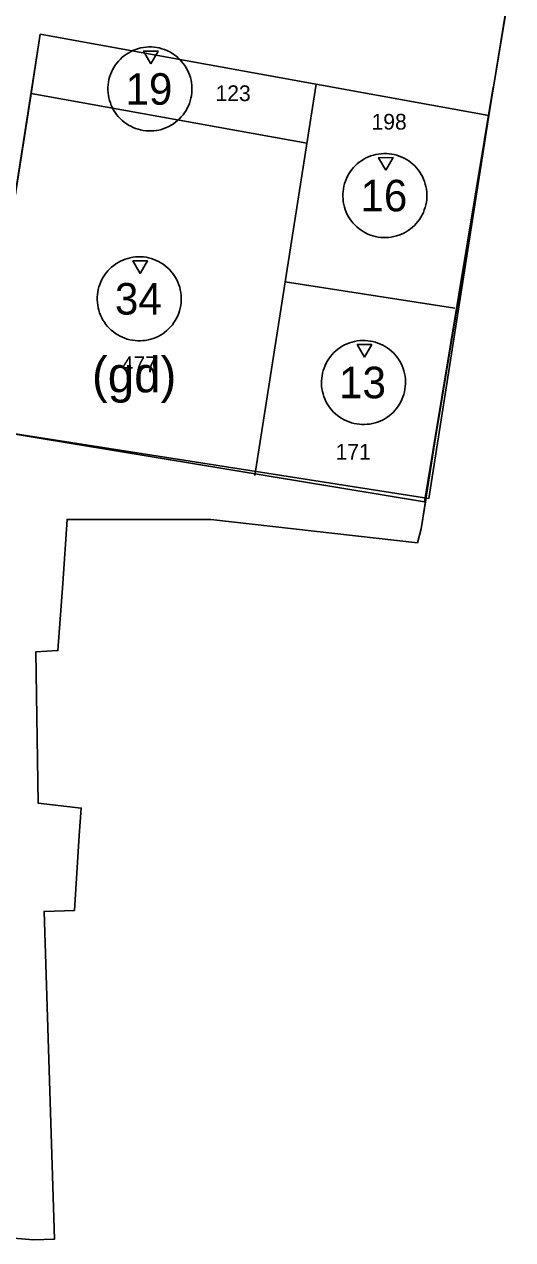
# Model space of a CAD drawing. Extents: x 104705 to 105186, y 424858 to 425816.
# Drawn here: x 105048.3 to 105083.1, y 424958.5 to 425045.2 of the extents above; entities that cross this region are included whole.
import ezdxf

# ---------------------------------------------------------------- set-up
doc = ezdxf.new("R2010")
doc.units = 0
for name, color, linetype in [('BP_ALG_bestemminggrens', 7, 'Continuous'), ('BP_BPG_Plangebied', 7, 'Continuous'), ('BP_BV_Bouwvlak', 7, 'Continuous'), ('BP_DB_Waarde - Archeologie - 3', 7, 'Continuous'), ('BP_EB_Verkeer', 7, 'Continuous'), ('BP_EB_Wonen', 7, 'Continuous'), ('BP_FA_gemengd', 7, 'Continuous'), ('BP_MV_maatvoering', 7, 'Continuous'), ('BP_TXT_tekst', 7, 'Continuous'), ('Default', 7, 'Continuous')]:
    doc.layers.add(name, color=color, linetype=linetype)

msp = doc.modelspace()

# ---------------------------------------------------------------- linework, layer by layer
at = {"layer": 'BP_ALG_bestemminggrens'}
for p, q in [((105046.867, 425028.264), (105049.408, 425044.533)), ((105081.418, 425038.738), (105049.408, 425044.533)), ((105081.418, 425038.738), (105076.846, 425011.136)), ((105045.014, 425016.408), (105076.846, 425011.136)), ((105045.014, 425016.407), (105076.846, 425011.136)), ((105076.846, 425011.136), (105076.846, 425011.136))]:
    msp.add_line(p, q, dxfattribs=at)
msp.add_lwpolyline([(105050.429, 424958.51), (105049.681, 424981.898), (105051.841, 424981.967)], dxfattribs=at)
at = {"layer": 'BP_BPG_Plangebied'}
msp.add_line((105051.841, 424981.967), (105051.841, 424981.967), dxfattribs=at)
for points in [[(105076.336, 425008.227), (105076.608, 425009.22), (105077.579, 425015.433), (105083.131, 425049.138)], [(105051.841, 424981.967), (105052.177, 424987.331), (105052.335, 424989.277), (105049.259, 424989.62), (105049.088, 425000.426), (105050.662, 425000.525), (105051.005, 425005.321), (105051.324, 425009.889), (105061.571, 425009.88), (105076.336, 425008.227)], [(105051.841, 424981.967), (105049.681, 424981.898), (105050.429, 424958.51)], [(104992.458, 424966.409), (105038.397, 424959.322), (105048.93, 424958.462), (105050.429, 424958.51)]]:
    msp.add_lwpolyline(points, dxfattribs=at)
at = {"layer": 'BP_BV_Bouwvlak'}
for p, q in [((105046.867, 425028.264), (105049.409, 425044.533)), ((105049.408, 425044.533), (105081.418, 425038.738)), ((105081.749, 425040.746), (105076.846, 425011.136)), ((105076.846, 425011.136), (105045.014, 425016.407))]:
    msp.add_line(p, q, dxfattribs=at)
at = {"layer": 'BP_DB_Waarde - Archeologie - 3'}
msp.add_line((105049.681, 424981.898), (105051.841, 424981.967), dxfattribs=at)
for points in [[(105076.336, 425008.227), (105076.608, 425009.22), (105077.579, 425015.433), (105083.131, 425049.138)], [(105051.841, 424981.967), (105052.177, 424987.331), (105052.335, 424989.277), (105049.259, 424989.62), (105049.088, 425000.426), (105050.662, 425000.525), (105051.005, 425005.321), (105051.324, 425009.889), (105061.571, 425009.88), (105076.336, 425008.227)], [(104992.458, 424966.409), (105038.397, 424959.322), (105048.93, 424958.462), (105050.429, 424958.51), (105049.681, 424981.898), (105049.681, 424981.898)]]:
    msp.add_lwpolyline(points, dxfattribs=at)
at = {"layer": 'BP_EB_Verkeer'}
for p, q in [((105081.418, 425038.738), (105083.131, 425049.138)), ((105048.674, 425039.829), (105049.408, 425044.533)), ((105049.408, 425044.533), (105081.418, 425038.738)), ((105046.866, 425028.264), (105048.674, 425039.829)), ((105064.746, 425013.14), (105045.014, 425016.408)), ((105076.846, 425011.136), (105064.746, 425013.14)), ((105076.608, 425009.22), (105076.951, 425011.417)), ((105076.894, 425011.426), (105076.846, 425011.136)), ((105076.951, 425011.417), (105076.894, 425011.426)), ((105061.571, 425009.88), (105076.336, 425008.227)), ((105076.336, 425008.227), (105076.608, 425009.22)), ((105050.662, 425000.525), (105051.005, 425005.321)), ((105049.088, 425000.426), (105050.662, 425000.525)), ((105049.259, 424989.62), (105049.088, 425000.426)), ((105051.841, 424981.967), (105052.177, 424987.331)), ((105049.681, 424981.898), (105051.841, 424981.967)), ((105050.429, 424958.51), (105049.681, 424981.898))]:
    msp.add_line(p, q, dxfattribs=at)
for points in [[(105051.005, 425005.321), (105051.324, 425009.889), (105061.571, 425009.88)], [(105052.177, 424987.331), (105052.335, 424989.277), (105049.259, 424989.62)], [(105041.81, 424959.043), (105048.93, 424958.462), (105050.429, 424958.51)]]:
    msp.add_lwpolyline(points, dxfattribs=at)
at = {"layer": 'BP_EB_Wonen'}
for points in [[(105077.145, 425011.387), (105081.418, 425038.738), (105049.408, 425044.533), (105049.287, 425043.758), (105046.856, 425028.204), (105015.703, 425033.072), (105014.92, 425028), (105009.674, 425028.81), (105008.627, 425022.021), (105005.662, 425022.479), (105002.768, 425003.717), (104999.803, 425004.175), (104994.246, 424968.157), (105006.105, 424966.327), (105005.8, 424964.351), (105038.397, 424959.322)], [(105038.397, 424959.322), (105041.81, 424959.043), (105043.061, 424970.744), (105038.007, 424971.524), (105008.124, 424976.134), (105012.156, 425002.269), (105015.121, 425001.811), (105018.016, 425020.573), (105045.014, 425016.407), (105077.145, 425011.387)]]:
    msp.add_lwpolyline(points, dxfattribs=at)
at = {"layer": 'BP_FA_gemengd'}
msp.add_lwpolyline([(105045.014, 425016.408), (105077.145, 425011.387), (105081.418, 425038.738), (105049.408, 425044.533), (105049.287, 425043.758), (105046.856, 425028.204), (105015.703, 425033.072), (105014.92, 425028), (105009.674, 425028.81), (105008.627, 425022.021), (105045.066, 425016.4)], dxfattribs=at)
at = {"layer": 'BP_MV_maatvoering'}
for p, q in [((105048.747, 425040.306), (105068.434, 425036.742)), ((105069.094, 425040.969), (105064.729, 425013.03)), ((105066.89, 425026.862), (105079.007, 425024.969))]:
    msp.add_line(p, q, dxfattribs=at)
for points in [[(105059.901, 425039.245), (105059.81, 425039.08), (105059.708, 425038.921), (105059.597, 425038.77), (105059.475, 425038.626), (105059.346, 425038.489), (105059.208, 425038.36), (105059.063, 425038.24), (105058.91, 425038.131), (105058.749, 425038.03), (105058.584, 425037.94), (105058.413, 425037.861), (105058.238, 425037.793), (105058.058, 425037.736), (105057.875, 425037.69), (105057.69, 425037.655), (105057.503, 425037.633), (105057.315, 425037.622), (105057.126, 425037.622), (105056.939, 425037.636), (105056.751, 425037.66), (105056.567, 425037.696), (105056.384, 425037.744), (105056.205, 425037.804), (105056.03, 425037.874), (105055.86, 425037.955), (105055.695, 425038.047), (105055.536, 425038.149), (105055.385, 425038.26), (105055.241, 425038.381), (105055.104, 425038.51), (105054.975, 425038.648), (105054.855, 425038.794), (105054.746, 425038.947), (105054.645, 425039.107), (105054.555, 425039.272), (105054.476, 425039.443), (105054.408, 425039.619), (105054.351, 425039.799), (105054.305, 425039.982), (105054.27, 425040.166), (105054.248, 425040.354), (105054.237, 425040.541), (105054.237, 425040.73), (105054.251, 425040.918), (105054.275, 425041.105), (105054.311, 425041.29), (105054.359, 425041.473), (105054.419, 425041.651), (105054.489, 425041.827), (105054.57, 425041.996), (105054.662, 425042.161), (105054.764, 425042.32), (105054.875, 425042.472), (105054.996, 425042.616), (105055.125, 425042.752), (105055.263, 425042.881), (105055.409, 425043.001), (105055.562, 425043.111), (105055.722, 425043.211), (105055.887, 425043.301), (105056.058, 425043.381), (105056.234, 425043.448), (105056.414, 425043.505), (105056.597, 425043.552), (105056.781, 425043.586), (105056.969, 425043.609), (105057.156, 425043.619), (105057.345, 425043.619), (105057.533, 425043.606), (105057.72, 425043.582), (105057.905, 425043.546), (105058.088, 425043.498), (105058.266, 425043.438), (105058.442, 425043.367), (105058.611, 425043.286), (105058.776, 425043.195), (105058.935, 425043.093), (105059.087, 425042.982), (105059.231, 425042.86), (105059.367, 425042.731), (105059.496, 425042.593), (105059.616, 425042.448), (105059.726, 425042.295), (105059.826, 425042.134), (105059.916, 425041.969), (105059.996, 425041.798), (105060.063, 425041.623), (105060.12, 425041.443), (105060.167, 425041.26), (105060.201, 425041.075), (105060.224, 425040.888), (105060.234, 425040.7), (105060.234, 425040.511), (105060.221, 425040.324), (105060.197, 425040.136), (105060.161, 425039.952), (105060.113, 425039.769), (105060.053, 425039.59), (105059.982, 425039.415)], [(105057.305, 425042.424), (105056.783, 425043.321), (105057.822, 425043.325)], [(105076.672, 425031.636), (105076.58, 425031.471), (105076.478, 425031.312), (105076.367, 425031.16), (105076.246, 425031.016), (105076.117, 425030.88), (105075.979, 425030.751), (105075.833, 425030.631), (105075.68, 425030.521), (105075.52, 425030.421), (105075.355, 425030.331), (105075.184, 425030.251), (105075.008, 425030.184), (105074.828, 425030.127), (105074.645, 425030.08), (105074.461, 425030.046), (105074.273, 425030.023), (105074.086, 425030.013), (105073.897, 425030.013), (105073.709, 425030.026), (105073.522, 425030.05), (105073.337, 425030.086), (105073.154, 425030.134), (105072.976, 425030.194), (105072.8, 425030.265), (105072.631, 425030.346), (105072.466, 425030.437), (105072.307, 425030.539), (105072.155, 425030.65), (105072.011, 425030.772), (105071.875, 425030.901), (105071.746, 425031.039), (105071.626, 425031.184), (105071.516, 425031.337), (105071.416, 425031.498), (105071.326, 425031.663), (105071.246, 425031.834), (105071.179, 425032.009), (105071.122, 425032.189), (105071.075, 425032.372), (105071.041, 425032.557), (105071.018, 425032.744), (105071.008, 425032.932), (105071.008, 425033.121), (105071.021, 425033.308), (105071.045, 425033.496), (105071.081, 425033.68), (105071.129, 425033.863), (105071.189, 425034.042), (105071.26, 425034.217), (105071.341, 425034.387), (105071.432, 425034.552), (105071.534, 425034.711), (105071.645, 425034.862), (105071.767, 425035.006), (105071.896, 425035.143), (105072.034, 425035.272), (105072.179, 425035.392), (105072.332, 425035.501), (105072.493, 425035.602), (105072.658, 425035.692), (105072.829, 425035.771), (105073.004, 425035.839), (105073.184, 425035.896), (105073.367, 425035.942), (105073.552, 425035.977), (105073.739, 425035.999), (105073.927, 425036.01), (105074.116, 425036.01), (105074.303, 425035.996), (105074.491, 425035.972), (105074.675, 425035.936), (105074.858, 425035.888), (105075.037, 425035.828), (105075.212, 425035.758), (105075.382, 425035.677), (105075.547, 425035.585), (105075.706, 425035.483), (105075.857, 425035.372), (105076.001, 425035.251), (105076.138, 425035.122), (105076.267, 425034.984), (105076.387, 425034.838), (105076.496, 425034.685), (105076.597, 425034.525), (105076.687, 425034.36), (105076.766, 425034.189), (105076.834, 425034.013), (105076.891, 425033.833), (105076.937, 425033.65), (105076.972, 425033.466), (105076.994, 425033.278), (105077.005, 425033.091), (105077.005, 425032.902), (105076.991, 425032.714), (105076.967, 425032.527), (105076.931, 425032.342), (105076.883, 425032.159), (105076.823, 425031.981), (105076.753, 425031.805)], [(105074.075, 425034.814), (105073.553, 425035.711), (105074.593, 425035.716)], [(105059.139, 425024.263), (105059.047, 425024.098), (105058.945, 425023.939), (105058.834, 425023.788), (105058.713, 425023.644), (105058.584, 425023.507), (105058.446, 425023.378), (105058.3, 425023.258), (105058.147, 425023.149), (105057.987, 425023.048), (105057.822, 425022.958), (105057.651, 425022.879), (105057.475, 425022.811), (105057.295, 425022.754), (105057.112, 425022.708), (105056.928, 425022.673), (105056.74, 425022.651), (105056.553, 425022.64), (105056.364, 425022.64), (105056.176, 425022.654), (105055.989, 425022.678), (105055.804, 425022.714), (105055.621, 425022.762), (105055.443, 425022.822), (105055.267, 425022.892), (105055.098, 425022.973), (105054.933, 425023.065), (105054.774, 425023.167), (105054.622, 425023.278), (105054.478, 425023.399), (105054.342, 425023.528), (105054.213, 425023.666), (105054.093, 425023.812), (105053.983, 425023.965), (105053.883, 425024.125), (105053.793, 425024.29), (105053.713, 425024.461), (105053.646, 425024.637), (105053.589, 425024.817), (105053.542, 425025), (105053.508, 425025.184), (105053.485, 425025.372), (105053.475, 425025.559), (105053.475, 425025.748), (105053.488, 425025.936), (105053.512, 425026.123), (105053.548, 425026.308), (105053.596, 425026.491), (105053.656, 425026.669), (105053.727, 425026.845), (105053.808, 425027.014), (105053.899, 425027.179), (105054.001, 425027.338), (105054.112, 425027.49), (105054.234, 425027.634), (105054.363, 425027.77), (105054.501, 425027.899), (105054.646, 425028.019), (105054.799, 425028.129), (105054.96, 425028.229), (105055.125, 425028.319), (105055.296, 425028.399), (105055.471, 425028.466), (105055.651, 425028.523), (105055.834, 425028.57), (105056.019, 425028.604), (105056.206, 425028.627), (105056.394, 425028.637), (105056.583, 425028.637), (105056.77, 425028.624), (105056.958, 425028.6), (105057.142, 425028.564), (105057.325, 425028.516), (105057.504, 425028.456), (105057.679, 425028.385), (105057.849, 425028.304), (105058.014, 425028.213), (105058.173, 425028.111), (105058.324, 425028), (105058.468, 425027.878), (105058.605, 425027.749), (105058.734, 425027.611), (105058.854, 425027.466), (105058.963, 425027.313), (105059.064, 425027.152), (105059.154, 425026.987), (105059.233, 425026.816), (105059.301, 425026.641), (105059.358, 425026.461), (105059.404, 425026.278), (105059.439, 425026.093), (105059.461, 425025.906), (105059.472, 425025.718), (105059.472, 425025.529), (105059.458, 425025.342), (105059.434, 425025.154), (105059.398, 425024.97), (105059.35, 425024.787), (105059.29, 425024.608), (105059.22, 425024.433)], [(105056.542, 425027.442), (105056.02, 425028.339), (105057.06, 425028.343)], [(105075.147, 425018.289), (105075.056, 425018.124), (105074.954, 425017.965), (105074.843, 425017.814), (105074.721, 425017.67), (105074.592, 425017.533), (105074.454, 425017.404), (105074.309, 425017.284), (105074.156, 425017.175), (105073.995, 425017.074), (105073.83, 425016.984), (105073.659, 425016.905), (105073.484, 425016.837), (105073.304, 425016.78), (105073.121, 425016.734), (105072.936, 425016.699), (105072.749, 425016.677), (105072.561, 425016.666), (105072.372, 425016.666), (105072.185, 425016.68), (105071.997, 425016.704), (105071.813, 425016.74), (105071.63, 425016.788), (105071.451, 425016.848), (105071.276, 425016.918), (105071.106, 425016.999), (105070.941, 425017.091), (105070.782, 425017.193), (105070.631, 425017.304), (105070.487, 425017.425), (105070.35, 425017.554), (105070.221, 425017.692), (105070.101, 425017.838), (105069.992, 425017.991), (105069.891, 425018.151), (105069.801, 425018.316), (105069.722, 425018.487), (105069.654, 425018.663), (105069.597, 425018.843), (105069.551, 425019.026), (105069.516, 425019.21), (105069.494, 425019.398), (105069.483, 425019.585), (105069.483, 425019.774), (105069.497, 425019.962), (105069.521, 425020.149), (105069.557, 425020.334), (105069.605, 425020.517), (105069.665, 425020.695), (105069.735, 425020.871), (105069.816, 425021.04), (105069.908, 425021.205), (105070.01, 425021.364), (105070.121, 425021.516), (105070.242, 425021.66), (105070.371, 425021.796), (105070.509, 425021.925), (105070.655, 425022.045), (105070.808, 425022.155), (105070.968, 425022.255), (105071.133, 425022.345), (105071.304, 425022.425), (105071.48, 425022.492), (105071.66, 425022.549), (105071.843, 425022.596), (105072.027, 425022.63), (105072.215, 425022.653), (105072.402, 425022.663), (105072.591, 425022.663), (105072.779, 425022.65), (105072.966, 425022.626), (105073.151, 425022.59), (105073.334, 425022.542), (105073.512, 425022.482), (105073.688, 425022.411), (105073.857, 425022.33), (105074.022, 425022.239), (105074.181, 425022.137), (105074.333, 425022.026), (105074.477, 425021.904), (105074.613, 425021.775), (105074.742, 425021.637), (105074.862, 425021.492), (105074.972, 425021.339), (105075.072, 425021.178), (105075.162, 425021.013), (105075.242, 425020.842), (105075.309, 425020.667), (105075.366, 425020.487), (105075.413, 425020.304), (105075.447, 425020.119), (105075.47, 425019.932), (105075.48, 425019.744), (105075.48, 425019.555), (105075.467, 425019.368), (105075.443, 425019.18), (105075.407, 425018.996), (105075.359, 425018.813), (105075.299, 425018.634), (105075.228, 425018.459)], [(105072.551, 425021.468), (105072.029, 425022.365), (105073.068, 425022.369)]]:
    msp.add_lwpolyline(points, close=True, dxfattribs=at)

# ---------------------------------------------------------------- texts
for s, p in [('19', (105055.491, 425039.496)), ('16', (105072.263, 425031.886)), ('34', (105054.735, 425024.514)), ('13', (105070.738, 425018.54))]:
    msp.add_text(s, height=2.25, dxfattribs=at).set_placement(p)
at = {"layer": 'BP_TXT_tekst'}
msp.add_text('(gd)', height=2.5312, dxfattribs=at).set_placement((105053.099, 425018.961))
at = {"layer": 'Default'}
for s, p in [('123', (105061.919, 425039.752)), ('198', (105073.055, 425037.719)), ('477', (105055.221, 425020.401)), ('171', (105070.49, 425014.152))]:
    msp.add_text(s, height=1.125, dxfattribs=at).set_placement(p)

doc.saveas('drawing.dxf')
